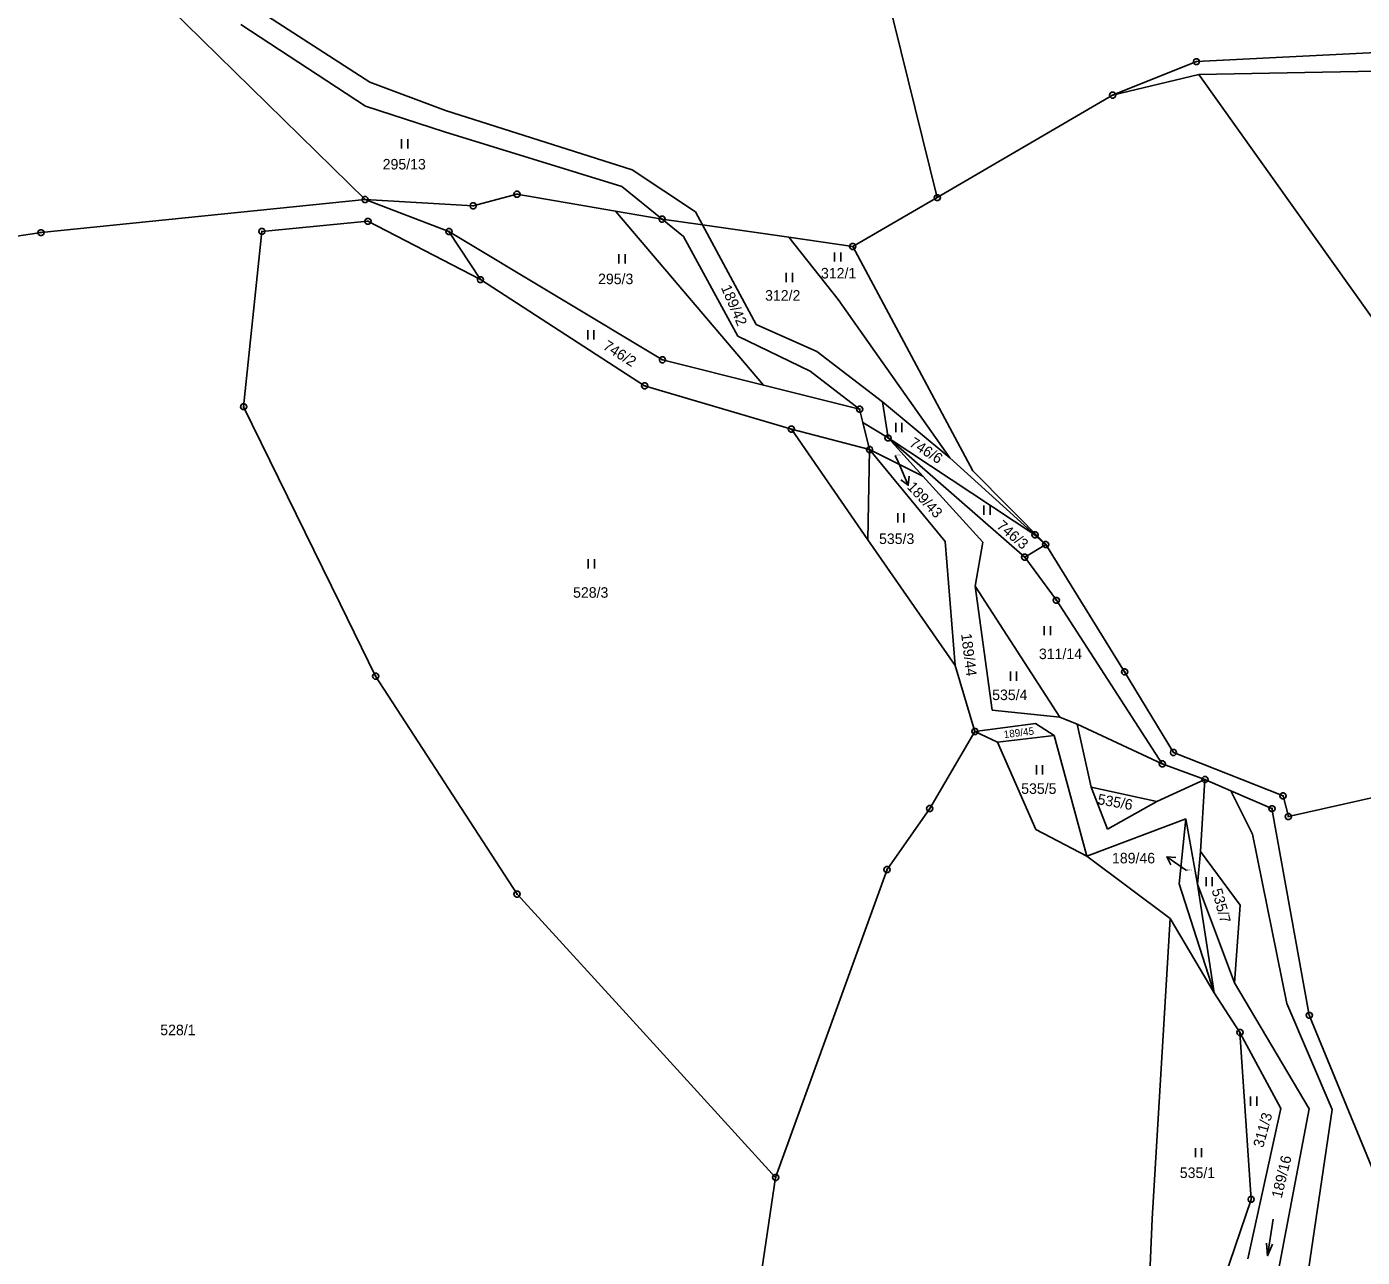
# Model space of a CAD drawing. Extents: x -694465 to -690527, y -983694 to -978978.
# Drawn here: x -693169.8 to -692954.4, y -981607.1 to -981408.6 of the extents above; entities that cross this region are included whole.
import ezdxf

# ---------------------------------------------------------------- set-up
doc = ezdxf.new("R2010")
doc.units = 0
for name, color, linetype in [('Vrstva 1', 7, 'Continuous'), ('Vrstva 16', 7, 'Continuous'), ('Vrstva 18', 7, 'Continuous'), ('Vrstva 24', 7, 'Continuous'), ('Vrstva 25', 7, 'Continuous'), ('Vrstva 29', 7, 'Continuous')]:
    doc.layers.add(name, color=color, linetype=linetype)

msp = doc.modelspace()

# ---------------------------------------------------------------- linework, layer by layer
at = {"layer": 'Vrstva 1'}
for p, q in [((-693134.8, -981469.92), (-693119.232, -981501.706)), ((-693119.232, -981501.706), (-693113.51, -981513.39)), ((-693073.111, -981567.809), (-693090.69, -981548.54)), ((-693073.111, -981567.809), (-693048.98, -981594.26))]:
    msp.add_line(p, q, dxfattribs=at)
for points in [[(-693022.9, -981436.19), (-693054.66, -981307.77)], [(-693157.32, -981395.14), (-693115.2, -981436.5)], [(-693114.44, -981417.54), (-693132.59, -981405.83)], [(-693135.27, -981408.27), (-693115.14, -981421.45)], [(-692939.29, -981412.15), (-692981.1, -981414.25)], [(-692981.1, -981414.25), (-692994.63, -981419.65)], [(-692980.73, -981416.34), (-692937.9, -981415.53)], [(-693102.26, -981422.13), (-693114.44, -981417.54)], [(-692994.63, -981419.65), (-692980.73, -981416.34)], [(-692980.73, -981416.34), (-692943.66, -981468.34)], [(-693022.9, -981436.19), (-692994.63, -981419.65)], [(-693115.14, -981421.45), (-693102.39, -981425.56)], [(-693072.14, -981431.7), (-693102.26, -981422.13)], [(-693102.39, -981425.56), (-693073.79, -981434.39)], [(-693061.92, -981438.49), (-693072.14, -981431.7)], [(-693073.79, -981434.39), (-693067.29, -981439.65)], [(-693167.48, -981441.84), (-693115.2, -981436.5)], [(-693115.2, -981436.5), (-693101.67, -981441.66)], [(-693115.2, -981436.5), (-693097.77, -981437.5)], [(-693097.77, -981437.5), (-693090.71, -981435.65)], [(-693090.71, -981435.65), (-693074.811, -981438.365)], [(-693036.55, -981444.07), (-693022.9, -981436.19)], [(-693074.811, -981438.365), (-693050.956, -981466.43)], [(-693074.811, -981438.365), (-693067.29, -981439.65)], [(-693060.79, -981440.59), (-693061.92, -981438.49)], [(-693131.85, -981441.63), (-693134.8, -981469.92)], [(-693114.75, -981440.01), (-693131.85, -981441.63)], [(-693096.59, -981449.42), (-693114.75, -981440.01)], [(-693101.67, -981441.66), (-693096.59, -981449.42)], [(-693067.24, -981462.34), (-693101.67, -981441.66)], [(-693067.29, -981439.65), (-693063.82, -981442.46)], [(-693060.79, -981440.59), (-693067.29, -981439.65)], [(-693052.11, -981456.64), (-693060.79, -981440.59)], [(-693060.79, -981440.59), (-693046.84, -981442.59)], [(-693193.84, -981445.81), (-693167.48, -981441.84)], [(-693063.82, -981442.46), (-693055.1, -981458.52)], [(-693038.92, -981452.6), (-693046.84, -981442.59)], [(-693046.84, -981442.59), (-693036.55, -981444.07)], [(-693017.17, -981480.29), (-693036.55, -981444.07)], [(-693096.59, -981449.42), (-693070.11, -981466.54)], [(-693020.9, -981478.15), (-693038.92, -981452.6)], [(-693042.33, -981461.03), (-693052.11, -981456.64)], [(-693055.1, -981458.52), (-693043.42, -981464.21)], [(-693031.73, -981469.11), (-693042.33, -981461.03)], [(-693050.956, -981466.43), (-693067.24, -981462.34)], [(-693043.42, -981464.21), (-693035.43, -981470.33)], [(-693070.11, -981466.54), (-693046.44, -981473.53)], [(-693035.43, -981470.33), (-693050.956, -981466.43)], [(-693020.9, -981478.15), (-693031.73, -981469.11)], [(-693030.85, -981474.96), (-693031.73, -981469.11)], [(-693035.43, -981470.33), (-693034.9, -981472.48)], [(-693046.44, -981473.53), (-693034.085, -981491.388)], [(-693033.84, -981476.84), (-693046.44, -981473.53)], [(-693034.9, -981472.48), (-693033.84, -981476.84)], [(-693030.85, -981474.96), (-693034.9, -981472.48)], [(-693025.26, -981481.11), (-693030.85, -981474.96)], [(-693030.85, -981474.96), (-693008.81, -981494.18)], [(-693030.85, -981474.96), (-693007.15, -981490.58)], [(-693033.84, -981476.84), (-693034.085, -981491.388)], [(-693033.84, -981476.84), (-693021.66, -981491.66)], [(-693033.84, -981476.84), (-693025.26, -981481.11)], [(-693007.15, -981490.58), (-693020.9, -981478.15)], [(-693005.42, -981492.15), (-693017.17, -981480.29)], [(-693015.58, -981491.76), (-693025.26, -981481.11)], [(-693005.42, -981492.15), (-693007.15, -981490.58)], [(-693034.085, -981491.388), (-693020.04, -981511.69)], [(-693021.66, -981491.66), (-693020.04, -981511.69)], [(-693016.81, -981498.86), (-693015.58, -981491.76)], [(-693008.81, -981494.18), (-693005.42, -981492.15)], [(-692992.69, -981512.69), (-693005.42, -981492.15)], [(-693003.7, -981501.15), (-693008.81, -981494.18)], [(-693003.12, -981520.03), (-693016.81, -981498.86)], [(-693014.07, -981518.9), (-693016.81, -981498.86)], [(-692986.61, -981527.54), (-693003.7, -981501.15)], [(-693020.04, -981511.69), (-693016.84, -981522.31)], [(-692984.81, -981525.7), (-692992.69, -981512.69)], [(-693113.51, -981513.39), (-693090.69, -981548.54)], [(-693003.12, -981520.03), (-693014.07, -981518.9)], [(-693016.84, -981522.31), (-693007.09, -981521.04)], [(-693007.09, -981521.04), (-693004.04, -981522.98)], [(-693000.33, -981521.11), (-693003.12, -981520.03)], [(-692998.09, -981531.31), (-693000.33, -981521.11)], [(-692986.61, -981527.54), (-693000.33, -981521.11)], [(-693016.84, -981522.31), (-693024.13, -981534.74)], [(-693016.84, -981522.31), (-693013.19, -981524.04)], [(-693013.19, -981524.04), (-693004.04, -981522.98)], [(-693004.04, -981522.98), (-692998.81, -981542.42)], [(-693013.19, -981524.04), (-693006.99, -981538.14)], [(-692967.14, -981532.7), (-692984.81, -981525.7)], [(-692979.74, -981530.06), (-692986.61, -981527.54)], [(-692979.74, -981530.06), (-692987.48, -981533.62)], [(-692980.47, -981541.65), (-692979.74, -981530.06)], [(-692975.573, -981531.87), (-692979.74, -981530.06)], [(-692987.48, -981533.62), (-692998.09, -981531.31)], [(-692995.47, -981538.07), (-692998.09, -981531.31)], [(-692977.03, -981694.86), (-692959.202, -981667.527), (-692965.416, -981625.199), (-692959.202, -981583.293), (-692966.527, -981566.189), (-692972.077, -981538.868), (-692975.573, -981531.87)], [(-692968.92, -981534.76), (-692975.573, -981531.87)], [(-692945.88, -981531.47), (-692966.28, -981536.03)], [(-692987.48, -981533.62), (-692995.47, -981538.07)], [(-692966.28, -981536.03), (-692967.14, -981532.7)], [(-693024.13, -981534.74), (-693031.01, -981544.58)], [(-692998.81, -981542.42), (-692982.79, -981536.41)], [(-692982.79, -981536.41), (-692983.91, -981546.88)], [(-692980.95, -981546.93), (-692982.79, -981536.41)], [(-692962.9, -981568.1), (-692968.92, -981534.76)], [(-693006.99, -981538.14), (-692998.81, -981542.42)], [(-692998.81, -981542.42), (-692985.36, -981552.46)], [(-692980.95, -981546.93), (-692980.47, -981541.65)], [(-692974.04, -981550.31), (-692980.47, -981541.65)], [(-693031.01, -981544.58), (-693048.98, -981594.26)], [(-692983.91, -981546.88), (-692978.26, -981564.49)], [(-692974.95, -981562.86), (-692980.95, -981546.93)], [(-692978.26, -981564.49), (-692980.95, -981546.93)], [(-692974.95, -981562.86), (-692974.04, -981550.31)], [(-692985.36, -981552.46), (-692988.25, -981600.91)], [(-692985.36, -981552.46), (-692978.26, -981564.49)], [(-692978.26, -981564.49), (-692974.09, -981570.86)], [(-692962.93, -981583.2), (-692974.95, -981562.86)], [(-692948.71, -981602.54), (-692962.9, -981568.1)], [(-692972.28, -981597.79), (-692974.09, -981570.86)], [(-692974.09, -981570.86), (-692967.49, -981583.14)], [(-692967.49, -981583.14), (-692972.82, -981607.38)], [(-692968.67, -981613.44), (-692962.93, -981583.2)], [(-693048.98, -981594.26), (-693062.85, -981688)], [(-692980.99, -981623.42), (-692972.28, -981597.79)], [(-692988.25, -981600.91), (-692989.14, -981622.34)]]:
    msp.add_lwpolyline(points, dxfattribs=at)
at = {"layer": 'Vrstva 16'}
msp.add_line((-693029.68, -981477.8), (-693029.19, -981478.93), dxfattribs=at)
at = {"layer": 'Vrstva 24'}
for points in [[(-692980.946, -981413.774), (-692980.696, -981413.956), (-692980.6, -981414.25), (-692980.696, -981414.544), (-692980.946, -981414.726), (-692981.254, -981414.726), (-692981.504, -981414.544), (-692981.6, -981414.25), (-692981.504, -981413.956), (-692981.254, -981413.774)], [(-692994.476, -981419.174), (-692994.226, -981419.356), (-692994.13, -981419.65), (-692994.226, -981419.944), (-692994.476, -981420.126), (-692994.784, -981420.126), (-692995.034, -981419.944), (-692995.13, -981419.65), (-692995.034, -981419.356), (-692994.784, -981419.174)], [(-693090.556, -981435.174), (-693090.306, -981435.356), (-693090.21, -981435.65), (-693090.306, -981435.944), (-693090.556, -981436.126), (-693090.864, -981436.126), (-693091.114, -981435.944), (-693091.21, -981435.65), (-693091.114, -981435.356), (-693090.864, -981435.174)], [(-693115.046, -981436.024), (-693114.796, -981436.206), (-693114.7, -981436.5), (-693114.796, -981436.794), (-693115.046, -981436.976), (-693115.354, -981436.976), (-693115.604, -981436.794), (-693115.7, -981436.5), (-693115.604, -981436.206), (-693115.354, -981436.024)], [(-693097.616, -981437.024), (-693097.366, -981437.206), (-693097.27, -981437.5), (-693097.366, -981437.794), (-693097.616, -981437.976), (-693097.924, -981437.976), (-693098.174, -981437.794), (-693098.27, -981437.5), (-693098.174, -981437.206), (-693097.924, -981437.024)], [(-693022.746, -981435.714), (-693022.496, -981435.896), (-693022.4, -981436.19), (-693022.496, -981436.484), (-693022.746, -981436.666), (-693023.054, -981436.666), (-693023.304, -981436.484), (-693023.4, -981436.19), (-693023.304, -981435.896), (-693023.054, -981435.714)], [(-693114.596, -981439.534), (-693114.346, -981439.716), (-693114.25, -981440.01), (-693114.346, -981440.304), (-693114.596, -981440.486), (-693114.904, -981440.486), (-693115.154, -981440.304), (-693115.25, -981440.01), (-693115.154, -981439.716), (-693114.904, -981439.534)], [(-693067.136, -981439.174), (-693066.886, -981439.356), (-693066.79, -981439.65), (-693066.886, -981439.944), (-693067.136, -981440.126), (-693067.444, -981440.126), (-693067.694, -981439.944), (-693067.79, -981439.65), (-693067.694, -981439.356), (-693067.444, -981439.174)], [(-693167.326, -981441.364), (-693167.076, -981441.546), (-693166.98, -981441.84), (-693167.076, -981442.134), (-693167.326, -981442.316), (-693167.634, -981442.316), (-693167.884, -981442.134), (-693167.98, -981441.84), (-693167.884, -981441.546), (-693167.634, -981441.364)], [(-693131.696, -981441.154), (-693131.446, -981441.336), (-693131.35, -981441.63), (-693131.446, -981441.924), (-693131.696, -981442.106), (-693132.004, -981442.106), (-693132.254, -981441.924), (-693132.35, -981441.63), (-693132.254, -981441.336), (-693132.004, -981441.154)], [(-693101.516, -981441.184), (-693101.266, -981441.366), (-693101.17, -981441.66), (-693101.266, -981441.954), (-693101.516, -981442.136), (-693101.824, -981442.136), (-693102.074, -981441.954), (-693102.17, -981441.66), (-693102.074, -981441.366), (-693101.824, -981441.184)], [(-693036.396, -981443.594), (-693036.146, -981443.776), (-693036.05, -981444.07), (-693036.146, -981444.364), (-693036.396, -981444.546), (-693036.704, -981444.546), (-693036.954, -981444.364), (-693037.05, -981444.07), (-693036.954, -981443.776), (-693036.704, -981443.594)], [(-693096.436, -981448.944), (-693096.186, -981449.126), (-693096.09, -981449.42), (-693096.186, -981449.714), (-693096.436, -981449.896), (-693096.744, -981449.896), (-693096.994, -981449.714), (-693097.09, -981449.42), (-693096.994, -981449.126), (-693096.744, -981448.944)], [(-693067.086, -981461.864), (-693066.836, -981462.046), (-693066.74, -981462.34), (-693066.836, -981462.634), (-693067.086, -981462.816), (-693067.394, -981462.816), (-693067.644, -981462.634), (-693067.74, -981462.34), (-693067.644, -981462.046), (-693067.394, -981461.864)], [(-693069.956, -981466.064), (-693069.706, -981466.246), (-693069.61, -981466.54), (-693069.706, -981466.834), (-693069.956, -981467.016), (-693070.264, -981467.016), (-693070.514, -981466.834), (-693070.61, -981466.54), (-693070.514, -981466.246), (-693070.264, -981466.064)], [(-693134.646, -981469.444), (-693134.396, -981469.626), (-693134.3, -981469.92), (-693134.396, -981470.214), (-693134.646, -981470.396), (-693134.954, -981470.396), (-693135.204, -981470.214), (-693135.3, -981469.92), (-693135.204, -981469.626), (-693134.954, -981469.444)], [(-693035.276, -981469.854), (-693035.026, -981470.036), (-693034.93, -981470.33), (-693035.026, -981470.624), (-693035.276, -981470.806), (-693035.584, -981470.806), (-693035.834, -981470.624), (-693035.93, -981470.33), (-693035.834, -981470.036), (-693035.584, -981469.854)], [(-693046.286, -981473.054), (-693046.036, -981473.236), (-693045.94, -981473.53), (-693046.036, -981473.824), (-693046.286, -981474.006), (-693046.594, -981474.006), (-693046.844, -981473.824), (-693046.94, -981473.53), (-693046.844, -981473.236), (-693046.594, -981473.054)], [(-693030.696, -981474.484), (-693030.446, -981474.666), (-693030.35, -981474.96), (-693030.446, -981475.254), (-693030.696, -981475.436), (-693031.004, -981475.436), (-693031.254, -981475.254), (-693031.35, -981474.96), (-693031.254, -981474.666), (-693031.004, -981474.484)], [(-693033.686, -981476.364), (-693033.436, -981476.546), (-693033.34, -981476.84), (-693033.436, -981477.134), (-693033.686, -981477.316), (-693033.994, -981477.316), (-693034.244, -981477.134), (-693034.34, -981476.84), (-693034.244, -981476.546), (-693033.994, -981476.364)], [(-693006.996, -981490.104), (-693006.746, -981490.286), (-693006.65, -981490.58), (-693006.746, -981490.874), (-693006.996, -981491.056), (-693007.304, -981491.056), (-693007.554, -981490.874), (-693007.65, -981490.58), (-693007.554, -981490.286), (-693007.304, -981490.104)], [(-693005.266, -981491.674), (-693005.016, -981491.856), (-693004.92, -981492.15), (-693005.016, -981492.444), (-693005.266, -981492.626), (-693005.574, -981492.626), (-693005.824, -981492.444), (-693005.92, -981492.15), (-693005.824, -981491.856), (-693005.574, -981491.674)], [(-693008.656, -981493.704), (-693008.406, -981493.886), (-693008.31, -981494.18), (-693008.406, -981494.474), (-693008.656, -981494.656), (-693008.964, -981494.656), (-693009.214, -981494.474), (-693009.31, -981494.18), (-693009.214, -981493.886), (-693008.964, -981493.704)], [(-693003.546, -981500.674), (-693003.296, -981500.856), (-693003.2, -981501.15), (-693003.296, -981501.444), (-693003.546, -981501.626), (-693003.854, -981501.626), (-693004.104, -981501.444), (-693004.2, -981501.15), (-693004.104, -981500.856), (-693003.854, -981500.674)], [(-692992.536, -981512.214), (-692992.286, -981512.396), (-692992.19, -981512.69), (-692992.286, -981512.984), (-692992.536, -981513.166), (-692992.844, -981513.166), (-692993.094, -981512.984), (-692993.19, -981512.69), (-692993.094, -981512.396), (-692992.844, -981512.214)], [(-693113.356, -981512.914), (-693113.106, -981513.096), (-693113.01, -981513.39), (-693113.106, -981513.684), (-693113.356, -981513.866), (-693113.664, -981513.866), (-693113.914, -981513.684), (-693114.01, -981513.39), (-693113.914, -981513.096), (-693113.664, -981512.914)], [(-693016.686, -981521.834), (-693016.436, -981522.016), (-693016.34, -981522.31), (-693016.436, -981522.604), (-693016.686, -981522.786), (-693016.994, -981522.786), (-693017.244, -981522.604), (-693017.34, -981522.31), (-693017.244, -981522.016), (-693016.994, -981521.834)], [(-692984.656, -981525.224), (-692984.406, -981525.406), (-692984.31, -981525.7), (-692984.406, -981525.994), (-692984.656, -981526.176), (-692984.964, -981526.176), (-692985.214, -981525.994), (-692985.31, -981525.7), (-692985.214, -981525.406), (-692984.964, -981525.224)], [(-692986.456, -981527.064), (-692986.206, -981527.246), (-692986.11, -981527.54), (-692986.206, -981527.834), (-692986.456, -981528.016), (-692986.764, -981528.016), (-692987.014, -981527.834), (-692987.11, -981527.54), (-692987.014, -981527.246), (-692986.764, -981527.064)], [(-692979.586, -981529.584), (-692979.336, -981529.766), (-692979.24, -981530.06), (-692979.336, -981530.354), (-692979.586, -981530.536), (-692979.894, -981530.536), (-692980.144, -981530.354), (-692980.24, -981530.06), (-692980.144, -981529.766), (-692979.894, -981529.584)], [(-692966.986, -981532.224), (-692966.736, -981532.406), (-692966.64, -981532.7), (-692966.736, -981532.994), (-692966.986, -981533.176), (-692967.294, -981533.176), (-692967.544, -981532.994), (-692967.64, -981532.7), (-692967.544, -981532.406), (-692967.294, -981532.224)], [(-693023.976, -981534.264), (-693023.726, -981534.446), (-693023.63, -981534.74), (-693023.726, -981535.034), (-693023.976, -981535.216), (-693024.284, -981535.216), (-693024.534, -981535.034), (-693024.63, -981534.74), (-693024.534, -981534.446), (-693024.284, -981534.264)], [(-692968.766, -981534.284), (-692968.516, -981534.466), (-692968.42, -981534.76), (-692968.516, -981535.054), (-692968.766, -981535.236), (-692969.074, -981535.236), (-692969.324, -981535.054), (-692969.42, -981534.76), (-692969.324, -981534.466), (-692969.074, -981534.284)], [(-692966.126, -981535.554), (-692965.876, -981535.736), (-692965.78, -981536.03), (-692965.876, -981536.324), (-692966.126, -981536.506), (-692966.434, -981536.506), (-692966.684, -981536.324), (-692966.78, -981536.03), (-692966.684, -981535.736), (-692966.434, -981535.554)], [(-693030.856, -981544.104), (-693030.606, -981544.286), (-693030.51, -981544.58), (-693030.606, -981544.874), (-693030.856, -981545.056), (-693031.164, -981545.056), (-693031.414, -981544.874), (-693031.51, -981544.58), (-693031.414, -981544.286), (-693031.164, -981544.104)], [(-693090.536, -981548.064), (-693090.286, -981548.246), (-693090.19, -981548.54), (-693090.286, -981548.834), (-693090.536, -981549.016), (-693090.844, -981549.016), (-693091.094, -981548.834), (-693091.19, -981548.54), (-693091.094, -981548.246), (-693090.844, -981548.064)], [(-692962.746, -981567.624), (-692962.496, -981567.806), (-692962.4, -981568.1), (-692962.496, -981568.394), (-692962.746, -981568.576), (-692963.054, -981568.576), (-692963.304, -981568.394), (-692963.4, -981568.1), (-692963.304, -981567.806), (-692963.054, -981567.624)], [(-692973.936, -981570.384), (-692973.686, -981570.566), (-692973.59, -981570.86), (-692973.686, -981571.154), (-692973.936, -981571.336), (-692974.244, -981571.336), (-692974.494, -981571.154), (-692974.59, -981570.86), (-692974.494, -981570.566), (-692974.244, -981570.384)], [(-693048.826, -981593.784), (-693048.576, -981593.966), (-693048.48, -981594.26), (-693048.576, -981594.554), (-693048.826, -981594.736), (-693049.134, -981594.736), (-693049.384, -981594.554), (-693049.48, -981594.26), (-693049.384, -981593.966), (-693049.134, -981593.784)], [(-692972.126, -981597.314), (-692971.876, -981597.496), (-692971.78, -981597.79), (-692971.876, -981598.084), (-692972.126, -981598.266), (-692972.434, -981598.266), (-692972.684, -981598.084), (-692972.78, -981597.79), (-692972.684, -981597.496), (-692972.434, -981597.314)]]:
    msp.add_lwpolyline(points, close=True, dxfattribs=at)
for points in [[(-692981.219, -981414.25), (-692980.98, -981414.25)], [(-692994.749, -981419.65), (-692994.51, -981419.65)], [(-693115.319, -981436.5), (-693115.08, -981436.5)], [(-693090.829, -981435.65), (-693090.59, -981435.65)], [(-693023.019, -981436.19), (-693022.78, -981436.19)], [(-693097.889, -981437.5), (-693097.65, -981437.5)], [(-693131.969, -981441.63), (-693131.73, -981441.63)], [(-693114.869, -981440.01), (-693114.63, -981440.01)], [(-693101.789, -981441.66), (-693101.55, -981441.66)], [(-693067.409, -981439.65), (-693067.17, -981439.65)], [(-693167.599, -981441.84), (-693167.36, -981441.84)], [(-693036.669, -981444.07), (-693036.43, -981444.07)], [(-693096.709, -981449.42), (-693096.47, -981449.42)], [(-693067.359, -981462.34), (-693067.12, -981462.34)], [(-693070.229, -981466.54), (-693069.99, -981466.54)], [(-693134.919, -981469.92), (-693134.68, -981469.92)], [(-693035.549, -981470.33), (-693035.31, -981470.33)], [(-693046.559, -981473.53), (-693046.32, -981473.53)], [(-693030.969, -981474.96), (-693030.73, -981474.96)], [(-693033.959, -981476.84), (-693033.72, -981476.84)], [(-693007.269, -981490.58), (-693007.03, -981490.58)], [(-693005.539, -981492.15), (-693005.3, -981492.15)], [(-693008.929, -981494.18), (-693008.69, -981494.18)], [(-693003.819, -981501.15), (-693003.58, -981501.15)], [(-692992.809, -981512.69), (-692992.57, -981512.69)], [(-693113.629, -981513.39), (-693113.39, -981513.39)], [(-693016.959, -981522.31), (-693016.72, -981522.31)], [(-692984.929, -981525.7), (-692984.69, -981525.7)], [(-692986.729, -981527.54), (-692986.49, -981527.54)], [(-692979.859, -981530.06), (-692979.62, -981530.06)], [(-692967.259, -981532.7), (-692967.02, -981532.7)], [(-693024.249, -981534.74), (-693024.01, -981534.74)], [(-692969.039, -981534.76), (-692968.8, -981534.76)], [(-692966.399, -981536.03), (-692966.16, -981536.03)], [(-693031.129, -981544.58), (-693030.89, -981544.58)], [(-693090.809, -981548.54), (-693090.57, -981548.54)], [(-692963.019, -981568.1), (-692962.78, -981568.1)], [(-692974.209, -981570.86), (-692973.97, -981570.86)], [(-693049.099, -981594.26), (-693048.86, -981594.26)], [(-692972.399, -981597.79), (-692972.16, -981597.79)]]:
    msp.add_lwpolyline(points, dxfattribs=at)
at = {"layer": 'Vrstva 25'}
for points in [[(-693109.33, -981426.76), (-693109.33, -981428.26)], [(-693108.33, -981428.26), (-693108.33, -981426.76)], [(-693074.25, -981445.31), (-693074.25, -981446.81)], [(-693073.25, -981446.81), (-693073.25, -981445.31)], [(-693039.46, -981445.02), (-693039.46, -981446.52)], [(-693038.46, -981446.52), (-693038.46, -981445.02)], [(-693047.28, -981448.31), (-693047.28, -981449.81)], [(-693046.28, -981449.81), (-693046.28, -981448.31)], [(-693079.28, -981457.59), (-693079.28, -981459.09)], [(-693078.28, -981459.09), (-693078.28, -981457.59)], [(-693029.6, -981472.52), (-693029.6, -981474.02)], [(-693028.6, -981474.02), (-693028.6, -981472.52)], [(-693015.39, -981485.87), (-693015.39, -981487.37)], [(-693014.39, -981487.37), (-693014.39, -981485.87)], [(-693029.29, -981487.09), (-693029.29, -981488.59)], [(-693028.29, -981488.59), (-693028.29, -981487.09)], [(-693079.2, -981494.51), (-693079.2, -981496.01)], [(-693078.2, -981496.01), (-693078.2, -981494.51)], [(-693005.67, -981505.3), (-693005.67, -981506.8)], [(-693004.67, -981506.8), (-693004.67, -981505.3)], [(-693011.12, -981512.63), (-693011.12, -981514.13)], [(-693010.12, -981514.13), (-693010.12, -981512.63)], [(-693006.93, -981527.77), (-693006.93, -981529.27)], [(-693005.93, -981529.27), (-693005.93, -981527.77)], [(-692979.55, -981545.79), (-692979.55, -981547.29)], [(-692978.55, -981547.29), (-692978.55, -981545.79)], [(-692972.38, -981581.18), (-692972.38, -981582.68)], [(-692971.38, -981582.68), (-692971.38, -981581.18)], [(-692981.27, -981589.51), (-692981.27, -981591.01)], [(-692980.27, -981591.01), (-692980.27, -981589.51)], [(-692968.706, -981600.966), (-692969.634, -981606.894)], [(-692968.831, -981604.995), (-692969.634, -981606.894), (-692969.819, -981604.841)]]:
    msp.add_lwpolyline(points, dxfattribs=at)
at = {"layer": 'Vrstva 29'}
for points in [[(-693029.19, -981478.93), (-693027.601, -981482.601), (-693027.429, -981481.11)], [(-693028.806, -981481.706), (-693027.601, -981482.601)], [(-692982.73, -981544.76), (-692985.854, -981542.526), (-692985.257, -981543.838)], [(-692984.42, -981542.667), (-692985.854, -981542.526)]]:
    msp.add_lwpolyline(points, dxfattribs=at)

# ---------------------------------------------------------------- texts
at = {"layer": 'Vrstva 16'}
msp.add_text('189/43', height=1.7, rotation=313.17873, dxfattribs=at).set_placement((-693027.901, -981482.96))
msp.add_text('189/46', height=1.7, dxfattribs=at).set_placement((-692994.724, -981543.59))
at = {"layer": 'Vrstva 18'}
for s, height, p in [('295/13', 1.7, (-693112.363, -981431.65)), ('312/1', 1.7, (-693041.668, -981449.23)), ('295/3', 1.7, (-693077.621, -981450.15)), ('312/2', 1.7, (-693050.679, -981452.81)), ('189/43', 0.2, (-693029.634, -981477.8)), ('535/3', 1.7, (-693032.301, -981492.07)), ('528/3', 1.7, (-693081.653, -981500.74)), ('311/14', 1.7, (-693006.513, -981510.64)), ('535/4', 1.7, (-693014.054, -981517.25)), ('535/5', 1.7, (-693009.371, -981532.38)), ('189/46', 0.2, (-692982.684, -981544.76)), ('528/1', 1.7, (-693148.242, -981571.31)), ('535/1', 1.7, (-692983.786, -981594.35))]:
    msp.add_text(s, height=height, dxfattribs=at).set_placement(p)
for s, height, rotation, p in [('189/42', 1.7, 293.41169, (-693057.834, -981450.69)), ('746/2', 1.7, 327.61727, (-693076.968, -981460.523)), ('746/6', 1.7, 327.61727, (-693027.55, -981476.167)), ('746/3', 1.7, 319.48127, (-693013.455, -981489.359)), ('189/44', 1.7, 277.19698, (-693019.071, -981506.59)), ('189/45', 1.2, 7.04738, (-693012.115, -981523.396)), ('535/6', 1.7, 350.07721, (-692997.15, -981534.027)), ('535/7', 1.7, 285.27569, (-692978.662, -981547.892)), ('311/3', 1.7, 74.7137, (-692970.348, -981589.568)), ('189/16', 1.7, 76.48987, (-692967.368, -981597.708))]:
    msp.add_text(s, height=height, rotation=rotation, dxfattribs=at).set_placement(p)

doc.saveas('drawing.dxf')
